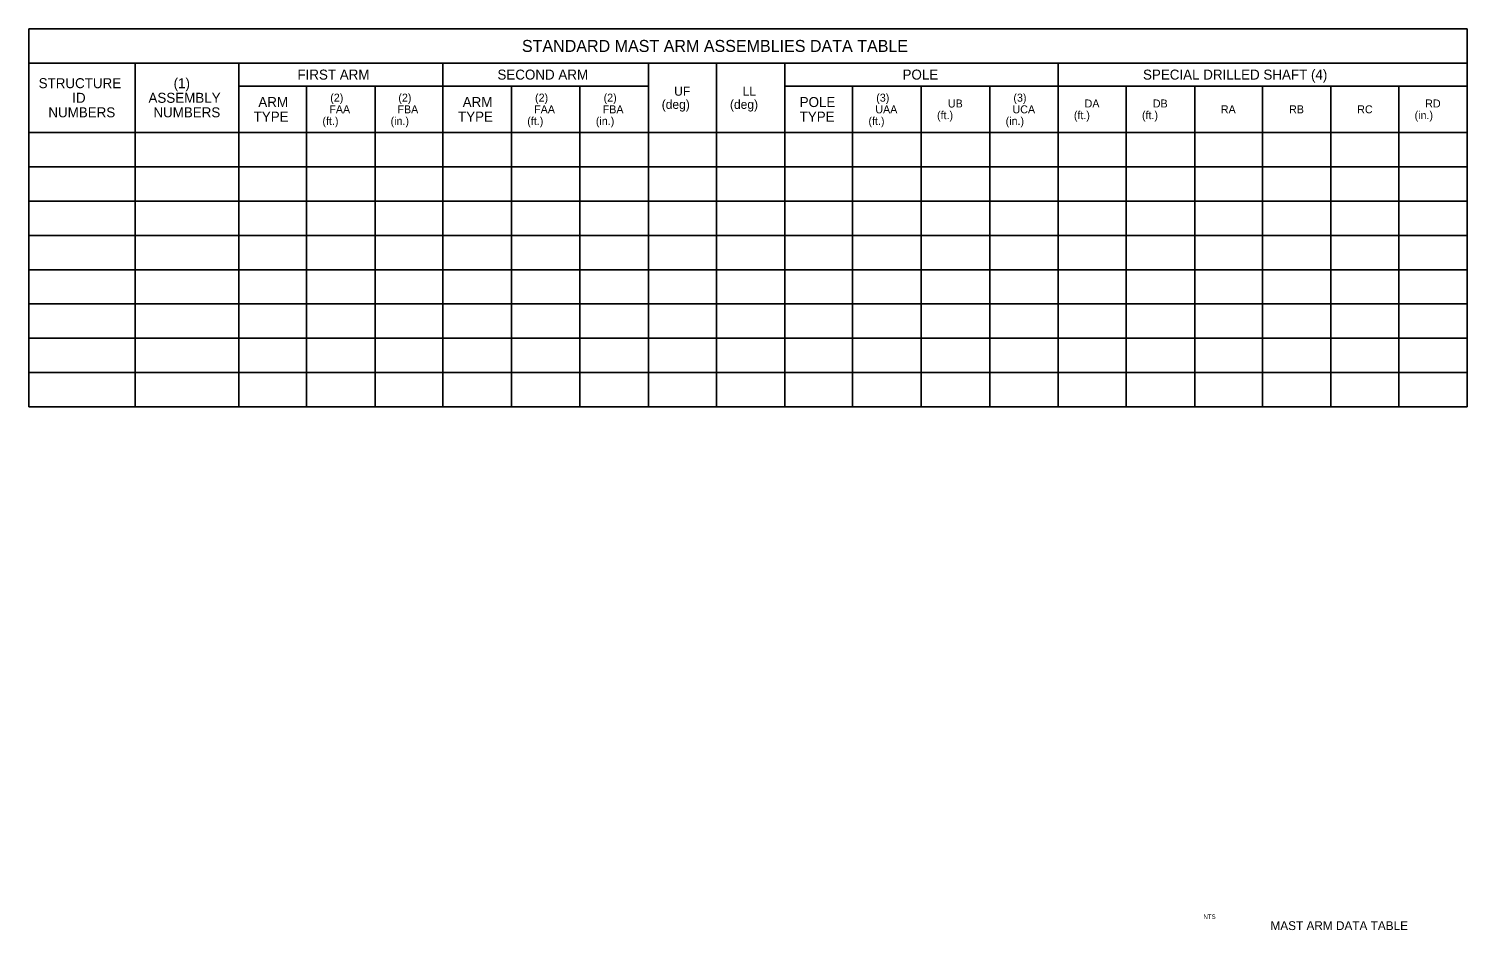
# Model space of a CAD drawing. Extents: x 1.5 to 14.1, y -0.2 to 7.7.
import ezdxf

# ---------------------------------------------------------------- set-up
doc = ezdxf.new("R2010")
doc.units = 0
for name, color, linetype in [('AdhocPoint_dp', 7, 'Continuous'), ('Default', 7, 'Continuous'), ('NonPlottingEle_dp', 7, 'Continuous'), ('PlotBorder_dp', 7, 'Continuous'), ('TextLabel', 7, 'Continuous')]:
    doc.layers.add(name, color=color, linetype=linetype)

msp = doc.modelspace()

# ---------------------------------------------------------------- linework, layer by layer
at = {"layer": 'AdhocPoint_dp'}
for p, q in [((1.507, 7.654), (14.092, 7.654)), ((1.507, 7.654), (1.507, 4.346)), ((14.092, 7.654), (14.092, 4.346)), ((1.507, 4.346), (14.092, 4.346))]:
    msp.add_line(p, q, dxfattribs=at)
at = {"layer": 'NonPlottingEle_dp'}
for p, q in [((1.507, 7.354), (14.092, 7.354)), ((1.507, 7.354), (14.092, 7.354)), ((2.437, 7.354), (2.437, 4.346)), ((2.437, 7.354), (2.437, 4.346)), ((3.344, 7.354), (3.344, 4.346)), ((3.344, 7.354), (3.344, 4.346)), ((5.129, 7.354), (5.129, 4.346)), ((5.129, 7.354), (5.129, 4.346)), ((6.929, 7.354), (6.929, 4.346)), ((6.929, 7.354), (6.929, 4.346)), ((7.522, 7.354), (7.522, 4.346)), ((7.522, 7.354), (7.522, 4.346)), ((8.122, 7.354), (8.122, 4.346)), ((8.122, 7.354), (8.122, 4.346)), ((10.514, 7.354), (10.514, 4.346)), ((10.514, 7.354), (10.514, 4.346)), ((3.344, 7.151), (6.929, 7.151)), ((3.344, 7.151), (6.929, 7.151)), ((3.937, 7.151), (3.937, 4.346)), ((3.937, 7.151), (3.937, 4.346)), ((4.537, 7.151), (4.537, 4.346)), ((4.537, 7.151), (4.537, 4.346)), ((5.729, 7.151), (5.729, 4.346)), ((5.729, 7.151), (5.729, 4.346)), ((6.329, 7.151), (6.329, 4.346)), ((6.329, 7.151), (6.329, 4.346)), ((8.122, 7.151), (14.092, 7.151)), ((8.122, 7.151), (14.092, 7.151)), ((8.714, 7.151), (8.714, 4.346)), ((8.714, 7.151), (8.714, 4.346)), ((9.314, 7.151), (9.314, 4.346)), ((9.314, 7.151), (9.314, 4.346)), ((9.914, 7.151), (9.914, 4.346)), ((9.914, 7.151), (9.914, 4.346)), ((11.107, 7.151), (11.107, 4.346)), ((11.107, 7.151), (11.107, 4.346)), ((11.707, 7.151), (11.707, 4.346)), ((11.707, 7.151), (11.707, 4.346)), ((12.299, 7.151), (12.299, 4.346)), ((12.299, 7.151), (12.299, 4.346)), ((12.899, 7.151), (12.899, 4.346)), ((12.899, 7.151), (12.899, 4.346)), ((13.492, 7.151), (13.492, 4.346)), ((13.492, 7.151), (13.492, 4.346)), ((1.507, 6.746), (14.092, 6.746)), ((1.507, 6.746), (14.092, 6.746))]:
    msp.add_line(p, q, dxfattribs=at)
at = {"layer": 'TextLabel'}
for p, q in [((1.507, 6.446), (14.092, 6.446)), ((1.507, 6.446), (14.092, 6.446)), ((1.507, 6.146), (14.092, 6.146)), ((1.507, 6.146), (14.092, 6.146)), ((1.507, 5.846), (14.092, 5.846)), ((1.507, 5.846), (14.092, 5.846)), ((1.507, 5.546), (14.092, 5.546)), ((1.507, 5.546), (14.092, 5.546)), ((1.507, 5.246), (14.092, 5.246)), ((1.507, 5.246), (14.092, 5.246)), ((1.507, 4.946), (14.092, 4.946)), ((1.507, 4.946), (14.092, 4.946)), ((1.507, 4.646), (14.092, 4.646)), ((1.507, 4.646), (14.092, 4.646))]:
    msp.add_line(p, q, dxfattribs=at)

# ---------------------------------------------------------------- texts
at = {"layer": 'Default'}
msp.add_text('NTS', height=0.0385, dxfattribs=at).set_placement((11.784, -0.133))
at = {"layer": 'PlotBorder_dp'}
for s, height, p in [('STANDARD MAST ARM ASSEMBLIES DATA TABLE', 0.105, (5.821, 7.451)), ('SPECIAL DRILLED SHAFT (4)', 0.0875, (11.255, 7.209)), ('STRUCTURE', 0.0875, (1.593, 7.134)), ('(1)', 0.0875, (2.774, 7.134)), ('FIRST ARM', 0.0875, (3.857, 7.209)), ('SECOND ARM', 0.0875, (5.607, 7.209)), ('POLE', 0.0875, (9.151, 7.209)), ('ID', 0.0875, (1.887, 7.006)), ('ASSEMBLY', 0.0875, (2.554, 7.006)), ('ARM', 0.0875, (3.515, 6.969)), ('(2)', 0.07, (4.144, 7.016)), ('(2)', 0.07, (4.74, 7.016)), ('ARM', 0.0875, (5.303, 6.969)), ('(2)', 0.07, (5.936, 7.016)), ('(2)', 0.07, (6.536, 7.016)), ('UF', 0.0788, (7.153, 7.068)), ('LL', 0.0788, (7.752, 7.068)), ('POLE', 0.0875, (8.251, 6.969)), ('(3)', 0.07, (8.921, 7.016)), ('(3)', 0.07, (10.121, 7.016)), ('NUMBERS', 0.0875, (1.678, 6.879)), ('NUMBERS', 0.0875, (2.597, 6.879)), ('TYPE', 0.0875, (3.474, 6.841)), ('FAA', 0.07, (4.136, 6.914)), ('FBA', 0.07, (4.732, 6.914)), ('TYPE', 0.0875, (5.262, 6.841)), ('FAA', 0.07, (5.928, 6.914)), ('FBA', 0.07, (6.528, 6.914)), ('(deg)', 0.0788, (7.044, 6.953)), ('(deg)', 0.0788, (7.641, 6.953)), ('TYPE', 0.0875, (8.251, 6.841)), ('UAA', 0.07, (8.913, 6.914)), ('(ft.)', 0.07, (9.453, 6.863)), ('UB', 0.07, (9.548, 6.965)), ('UCA', 0.07, (10.113, 6.914)), ('(ft.)', 0.07, (10.65, 6.863)), ('DA', 0.07, (10.744, 6.965)), ('(ft.)', 0.07, (11.246, 6.863)), ('DB', 0.07, (11.341, 6.965)), ('RA', 0.07, (11.936, 6.914)), ('RB', 0.07, (12.533, 6.914)), ('RC', 0.07, (13.129, 6.914)), ('(in.)', 0.07, (13.631, 6.863)), ('RD', 0.07, (13.724, 6.965)), ('(ft.)', 0.07, (4.076, 6.812)), ('(in.)', 0.07, (4.672, 6.812)), ('(ft.)', 0.07, (5.868, 6.812)), ('(in.)', 0.07, (6.468, 6.812)), ('(ft.)', 0.07, (8.853, 6.812)), ('(in.)', 0.07, (10.053, 6.812)), ('  MAST ARM DATA TABLE   ', 0.07709, (12.313, -0.231))]:
    msp.add_text(s, height=height, dxfattribs=at).set_placement(p)

doc.saveas('drawing.dxf')
